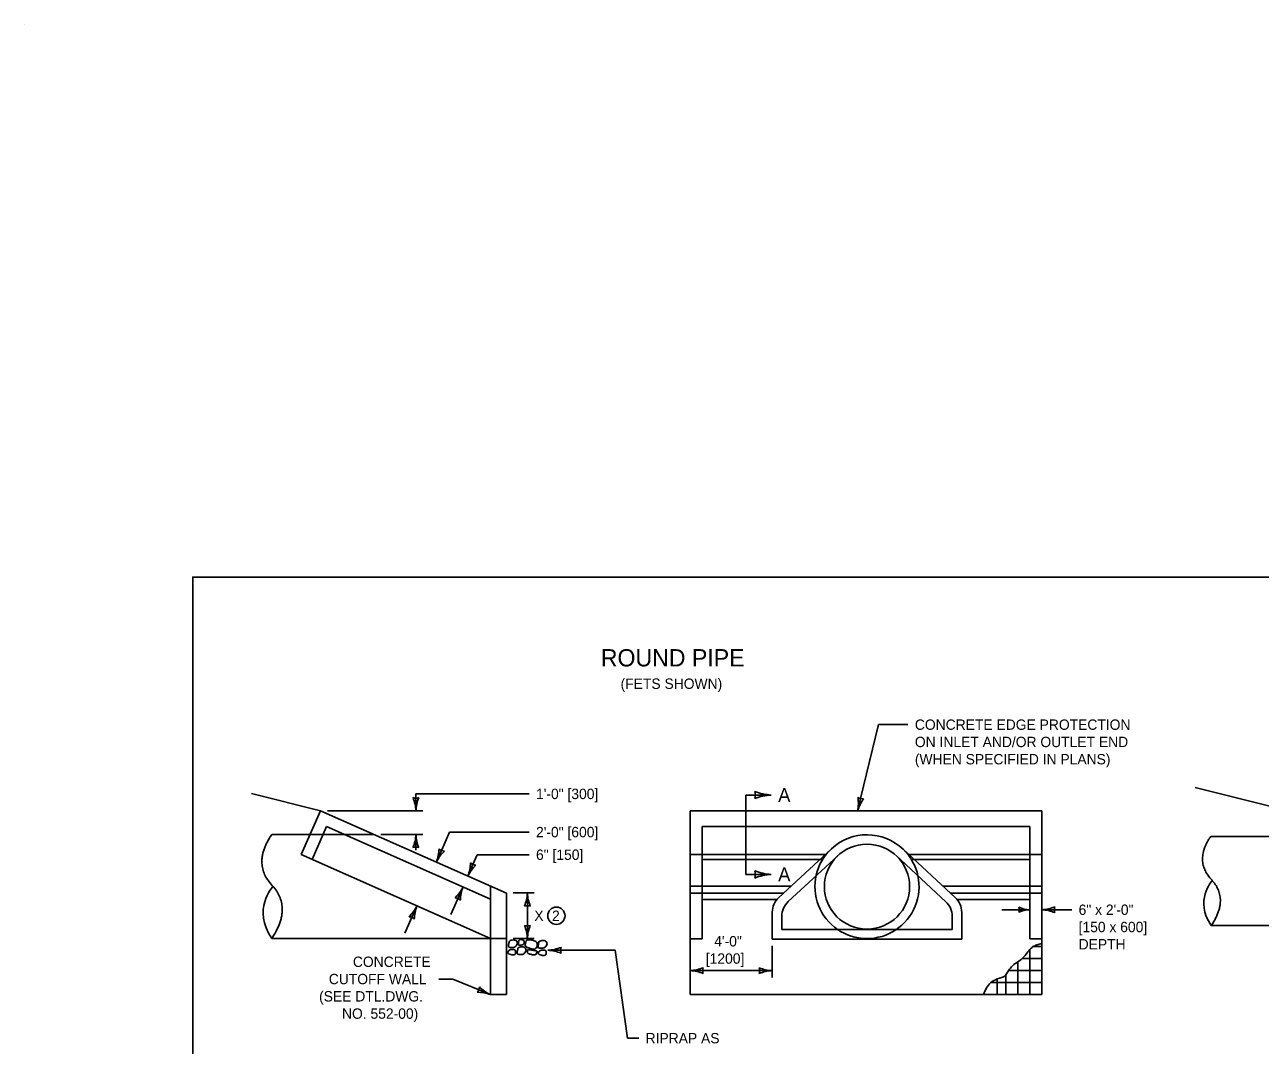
# Model space of a CAD drawing. Extents: x 49991.4 to 50021, y 49987.6 to 50011.4.
# Drawn here: x 50008.76 to 50015.92, y 50005.45 to 50011.36 of the extents above; entities that cross this region are included whole.
import ezdxf

# ---------------------------------------------------------------- set-up
doc = ezdxf.new("R2010")
doc.units = 0
for name, color, linetype in [('Level 1', 7, 'Continuous'), ('Level 2', 7, 'Continuous'), ('Level 3', 7, 'Continuous'), ('Level 4', 7, 'Continuous'), ('Level 6', 7, 'Continuous')]:
    doc.layers.add(name, color=color, linetype=linetype)

msp = doc.modelspace()

# ---------------------------------------------------------------- linework, layer by layer
at = {"layer": 'Level 1'}
for p, q in [((50008.7646, 50011.3628), (50008.7646, 50011.3628)), ((50010.477, 50006.8119), (50010.077, 50006.9119)), ((50016.1364, 50006.7969), (50015.5405, 50006.9461)), ((50010.477, 50006.8119), (50010.3648, 50006.558)), ((50011.5532, 50006.3359), (50010.477, 50006.8119)), ((50012.6169, 50006.8119), (50014.6523, 50006.8119)), ((50012.6169, 50005.7479), (50012.6169, 50006.8119)), ((50014.6523, 50005.7479), (50014.6523, 50006.8119)), ((50010.4164, 50006.6748), (50010.1952, 50006.6748)), ((50016.0887, 50006.6627), (50015.6302, 50006.6627)), ((50013.435, 50006.5923), (50013.1292, 50006.3081)), ((50013.8501, 50006.5889), (50014.1521, 50006.3081)), ((50011.4607, 50006.0733), (50010.3648, 50006.558)), ((50013.4729, 50006.5528), (50013.1842, 50006.2861)), ((50013.8087, 50006.5527), (50014.0973, 50006.2855)), ((50011.4607, 50005.7479), (50011.4607, 50006.3768)), ((50012.6169, 50006.3755), (50013.2017, 50006.3755)), ((50014.0796, 50006.3755), (50014.6523, 50006.3755)), ((50011.5532, 50005.7479), (50011.5532, 50006.3359)), ((50012.6169, 50006.3359), (50013.1591, 50006.3359)), ((50014.1222, 50006.3359), (50014.6523, 50006.3359)), ((50013.0925, 50006.0692), (50013.0926, 50006.2242)), ((50013.1474, 50006.1239), (50013.1474, 50006.202)), ((50014.134, 50006.1239), (50014.1341, 50006.2015)), ((50014.1888, 50006.0692), (50014.1889, 50006.224)), ((50014.134, 50006.1239), (50013.1474, 50006.1239)), ((50017.1373, 50006.1472), (50015.6335, 50006.1472)), ((50011.4607, 50006.0733), (50010.1948, 50006.0733)), ((50011.619, 50006.0174), (50011.6203, 50006.0182)), ((50011.7402, 50006.0538), (50011.7415, 50006.0546)), ((50014.1888, 50006.0692), (50013.0925, 50006.0692)), ((50014.6015, 50006.0255), (50014.6523, 50006.0255)), ((50014.5395, 50005.9561), (50014.6523, 50005.9561)), ((50014.5829, 50005.7479), (50014.5829, 50006.0083)), ((50014.4599, 50005.8867), (50014.6523, 50005.8867)), ((50014.5135, 50005.7479), (50014.5135, 50005.9377)), ((50014.3576, 50005.8174), (50014.6523, 50005.8174)), ((50014.3937, 50005.7479), (50014.3937, 50005.8387)), ((50014.4442, 50005.7479), (50014.4442, 50005.8616)), ((50011.4607, 50005.7479), (50011.5532, 50005.7479)), ((50012.6169, 50005.7479), (50014.6523, 50005.7479))]:
    msp.add_line(p, q, dxfattribs=at)
msp.add_lwpolyline([(50020.9378, 50008.1646), (50009.7374, 50008.1646), (50009.7374, 49999.8856), (50020.9378, 49999.8856)], close=True, dxfattribs=at)
for centre, major_axis, start_param, end_param in [((50013.6407, 50006.3727), (0.3015, 0), 0.803192, 2.321661), ((50013.2077, 50006.2242), (-0.1151, 0), 5.463072, 6.283185), ((50014.0738, 50006.224), (0.1151, 0), 0, 0.82267), ((50013.2625, 50006.202), (-0.1151, 0), 5.460236, 6.283185), ((50014.019, 50006.2015), (0.1151, 0), 0, 0.822133)]:
    msp.add_ellipse(centre, major_axis=major_axis, ratio=0.996203, start_param=start_param, end_param=end_param, dxfattribs=at)
msp.add_ellipse((50013.6407, 50006.3727), major_axis=(0.2467, 0), ratio=0.996203, dxfattribs=at)
for points, degree in [([(50010.1948, 50006.0733), (50010.3154, 50006.2517), (50010.079, 50006.5076), (50010.1952, 50006.6748)], 2), ([(50015.6335, 50006.1472), (50015.7379, 50006.3016), (50015.5332, 50006.5232), (50015.6302, 50006.6627)], 2), ([(50010.202, 50006.3743), (50010.1995, 50006.3714), (50010.0786, 50006.2405), (50010.1948, 50006.0733)], 3), ([(50015.6397, 50006.4078), (50015.6375, 50006.4052), (50015.5329, 50006.292), (50015.6335, 50006.1472)], 3)]:
    msp.add_open_spline(points, degree=degree, dxfattribs=at)
for points in [[(50011.5703, 50006.0579), (50011.5809, 50006.0625), (50011.5936, 50006.0641), (50011.6069, 50006.0618), (50011.613, 50006.0566), (50011.617, 50006.0456), (50011.6124, 50006.0339), (50011.5994, 50006.0219), (50011.5871, 50006.0204), (50011.5744, 50006.0207), (50011.5664, 50006.0237), (50011.5652, 50006.0334), (50011.5667, 50006.0413), (50011.5685, 50006.0498), (50011.5703, 50006.0579)], [(50011.619, 50006.0174), (50011.6311, 50006.0224), (50011.6437, 50006.0242), (50011.6569, 50006.0217), (50011.6632, 50006.0165), (50011.6672, 50006.0055), (50011.6625, 50005.9938), (50011.6495, 50005.9819), (50011.6373, 50005.9802), (50011.6245, 50005.9807), (50011.6165, 50005.9835), (50011.6152, 50005.9932), (50011.6169, 50006.0012), (50011.6186, 50006.0098), (50011.6203, 50006.0182)], [(50011.626, 50006.0615), (50011.6317, 50006.066), (50011.6435, 50006.0652), (50011.6541, 50006.0607), (50011.6565, 50006.0487), (50011.6498, 50006.0372), (50011.6382, 50006.0339), (50011.6223, 50006.0365), (50011.6223, 50006.0442), (50011.6245, 50006.0519), (50011.6242, 50006.0597), (50011.6262, 50006.062)], [(50011.6618, 50006.0375), (50011.6665, 50006.0514), (50011.6717, 50006.0635), (50011.6792, 50006.0653), (50011.6956, 50006.0648), (50011.7147, 50006.0581), (50011.729, 50006.05), (50011.732, 50006.0339), (50011.7241, 50006.0157), (50011.7126, 50006.0114), (50011.6871, 50006.0171), (50011.6703, 50006.0227), (50011.6623, 50006.032), (50011.6618, 50006.0377)], [(50011.7402, 50006.0538), (50011.7523, 50006.0588), (50011.7649, 50006.0606), (50011.7781, 50006.0581), (50011.7844, 50006.0529), (50011.7884, 50006.0419), (50011.7837, 50006.0302), (50011.7707, 50006.0183), (50011.7585, 50006.0166), (50011.7457, 50006.0171), (50011.7377, 50006.0199), (50011.7364, 50006.0296), (50011.7381, 50006.0376), (50011.7398, 50006.0462), (50011.7415, 50006.0546)], [(50014.3937, 50005.8387), (50014.4442, 50005.8616), (50014.4599, 50005.8867), (50014.5135, 50005.9377), (50014.5395, 50005.9561), (50014.5829, 50006.0083), (50014.6015, 50006.0255)], [(50014.6015, 50006.0255), (50014.6239, 50006.036), (50014.6521, 50006.0419), (50014.6523, 50006.0419)], [(50011.5753, 50006.0083), (50011.5827, 50006.0092), (50011.5912, 50006.009), (50011.6002, 50006.0084), (50011.6045, 50006.0042), (50011.6055, 50005.9927), (50011.6054, 50005.9835), (50011.5953, 50005.9787), (50011.5731, 50005.9811), (50011.5616, 50005.9867), (50011.5624, 50005.9956), (50011.5677, 50006.0025), (50011.5765, 50006.0087)], [(50011.6795, 50006.0094), (50011.6914, 50006.0062), (50011.7093, 50006.0037), (50011.7281, 50006.0004), (50011.7314, 50005.9981), (50011.7281, 50005.987), (50011.7216, 50005.9797), (50011.7036, 50005.9789), (50011.6841, 50005.9843), (50011.6745, 50005.9893), (50011.6746, 50005.9985), (50011.6778, 50006.0076), (50011.6789, 50006.0094)], [(50011.7523, 50006.0045), (50011.7594, 50006.0057), (50011.768, 50006.0053), (50011.7772, 50006.0047), (50011.7814, 50006.0004), (50011.7824, 50005.9891), (50011.7822, 50005.9798), (50011.7721, 50005.975), (50011.7499, 50005.9773), (50011.7385, 50005.9829), (50011.7394, 50005.9918), (50011.7444, 50005.9987), (50011.7517, 50006.0044)], [(50014.3152, 50005.7479), (50014.3578, 50005.8175), (50014.3937, 50005.8387)]]:
    msp.add_spline(points, degree=3, dxfattribs=at)
at = {"layer": 'Level 2'}
msp.add_circle((50011.8424, 50006.2041), 0.05, dxfattribs=at)
at = {"layer": 'Level 3'}
for p, q in [((50013.7069, 50007.3106), (50013.5863, 50006.8119)), ((50013.7069, 50007.3106), (50013.8778, 50007.3106)), ((50011.0293, 50006.8119), (50011.0293, 50006.9097)), ((50011.0293, 50006.9097), (50011.6846, 50006.9097)), ((50010.517, 50006.8119), (50011.0693, 50006.8119)), ((50010.8269, 50006.6748), (50011.0692, 50006.6748)), ((50011.0292, 50006.5841), (50011.0292, 50006.6748)), ((50011.1478, 50006.5152), (50011.2245, 50006.6886)), ((50011.2245, 50006.6886), (50011.6846, 50006.6886)), ((50011.3303, 50006.4345), (50011.3845, 50006.5576)), ((50011.3845, 50006.5576), (50011.6846, 50006.5576)), ((50011.2323, 50006.2124), (50011.3023, 50006.3711)), ((50011.5932, 50006.336), (50011.7146, 50006.336)), ((50011.6746, 50006.336), (50011.6747, 50006.0723)), ((50010.9653, 50006.1028), (50011.0353, 50006.2614)), ((50014.4217, 50006.2391), (50014.5829, 50006.2391)), ((50014.6523, 50006.2391), (50014.8257, 50006.2391)), ((50011.5932, 50006.0723), (50011.7147, 50006.0723)), ((50013.0925, 50005.8466), (50013.0925, 50006.0292)), ((50011.7935, 50006.0044), (50012.1834, 50006.0044)), ((50012.1834, 50006.0044), (50012.2551, 50005.4954)), ((50013.0925, 50005.8866), (50012.6169, 50005.8866)), ((50011.1617, 50005.8378), (50011.2436, 50005.8378)), ((50011.2436, 50005.8378), (50011.4607, 50005.7479)), ((50012.2551, 50005.4954), (50012.3189, 50005.4954))]:
    msp.add_line(p, q, dxfattribs=at)
for centre, radius, start, end in [((50011.0293, 50006.9401), 0.0548, 252.13882, 287.86118), ((50010.7966, 50006.8004), 0.233, 2.82731, 22.07716), ((50011.2514, 50006.8027), 0.2223, 157.45601, 177.63952), ((50013.0976, 50007.1809), 0.2779, 247.45601, 267.63952), ((50012.9259, 50006.9032), 0.0685, 342.13882, 17.86118), ((50013.1006, 50006.6123), 0.2912, 92.82731, 112.07716), ((50013.3577, 50006.8568), 0.233, 348.8782, 8.12805), ((50013.7997, 50006.7495), 0.2223, 143.5069, 163.69041), ((50013.6172, 50006.9363), 0.0548, 238.18971, 273.91207), ((50010.8071, 50006.684), 0.2223, 337.45601, 357.63952), ((50011.2619, 50006.6863), 0.233, 182.82731, 202.07716), ((50011.0292, 50006.5466), 0.0548, 72.13882, 107.86118), ((50010.9303, 50006.5989), 0.233, 338.95328, 358.20312), ((50011.1997, 50006.6325), 0.0548, 228.26478, 263.98714), ((50011.3472, 50006.4169), 0.2223, 133.58197, 153.76548), ((50011.1127, 50006.5178), 0.233, 339.05124, 358.30109), ((50011.5299, 50006.3366), 0.2223, 133.67994, 153.86345), ((50011.382, 50006.5518), 0.0548, 228.36275, 264.08511), ((50013.0976, 50006.7214), 0.2779, 247.45601, 267.63952), ((50012.9259, 50006.4437), 0.0685, 342.13882, 17.86118), ((50013.1006, 50006.1528), 0.2912, 92.82731, 112.07716), ((50011.1028, 50006.4691), 0.2223, 313.64287, 333.82638), ((50011.2505, 50006.2538), 0.0548, 48.32568, 84.04804), ((50011.5198, 50006.2876), 0.233, 159.01417, 178.26402), ((50011.4525, 50006.3452), 0.2223, 337.45601, 357.63952), ((50011.9073, 50006.3475), 0.233, 182.82731, 202.07716), ((50010.8358, 50006.3596), 0.2223, 313.63372, 333.81723), ((50011.2529, 50006.178), 0.233, 159.00502, 178.25487), ((50011.6746, 50006.2078), 0.0548, 72.13882, 107.86118), ((50014.5905, 50006.4242), 0.1853, 247.45601, 267.63952), ((50014.4761, 50006.2391), 0.0456, 342.13882, 17.86118), ((50014.5925, 50006.0452), 0.1942, 92.82731, 112.07716), ((50014.6408, 50006.4718), 0.233, 272.82731, 292.07716), ((50014.6431, 50006.017), 0.2223, 67.45601, 87.63952), ((50014.7805, 50006.2391), 0.0548, 162.13882, 197.86118), ((50010.9836, 50006.1442), 0.0548, 48.31653, 84.03889), ((50011.6747, 50006.2005), 0.0548, 252.13882, 287.86118), ((50011.442, 50006.0608), 0.233, 2.82731, 22.07716), ((50011.8968, 50006.0631), 0.2223, 157.45601, 177.63952), ((50011.782, 50006.2371), 0.233, 272.82731, 292.07716), ((50011.9217, 50006.0044), 0.0548, 162.13882, 197.86118), ((50011.7843, 50005.7823), 0.2223, 67.45601, 87.63952), ((50012.6054, 50006.1193), 0.233, 272.82731, 292.07716), ((50012.6077, 50005.6645), 0.2223, 67.45601, 87.63952), ((50012.7451, 50005.8866), 0.0548, 162.13882, 197.86118), ((50013.1017, 50006.1087), 0.2223, 247.45601, 267.63952), ((50012.9643, 50005.8866), 0.0548, 342.13882, 17.86118), ((50013.104, 50005.6539), 0.233, 92.82731, 112.07716), ((50011.3422, 50005.7969), 0.0548, 319.64694, 355.3693), ((50011.3842, 50005.5392), 0.2223, 69.8686, 90.05211), ((50011.5603, 50005.9585), 0.233, 225.43096, 244.68081)]:
    msp.add_arc(centre, radius, start, end, dxfattribs=at)
at = {"layer": 'Level 4'}
for p, q in [((50010.4164, 50006.6748), (50010.787, 50006.6748)), ((50010.5124, 50006.7204), (50010.4282, 50006.5299)), ((50011.4607, 50006.301), (50010.5124, 50006.7204)), ((50012.6864, 50006.7204), (50014.5829, 50006.7204)), ((50012.6864, 50006.0709), (50012.6864, 50006.7204)), ((50014.5829, 50006.0709), (50014.5829, 50006.7204)), ((50012.6169, 50006.558), (50013.4034, 50006.558)), ((50012.6864, 50006.5301), (50013.384, 50006.5301)), ((50013.878, 50006.558), (50014.6523, 50006.558)), ((50013.8975, 50006.5301), (50014.5829, 50006.5301)), ((50012.6864, 50006.2975), (50013.1192, 50006.2975)), ((50014.1622, 50006.2975), (50014.5829, 50006.2975)), ((50011.5532, 50006.0733), (50011.4607, 50006.0733)), ((50012.6169, 50006.0709), (50012.6864, 50006.0709)), ((50014.5829, 50006.0709), (50014.6523, 50006.0709))]:
    msp.add_line(p, q, dxfattribs=at)
msp.add_ellipse((50013.6407, 50006.3727), major_axis=(0.3015, 0), ratio=0.996203, start_param=2.321661, end_param=7.086377, dxfattribs=at)
at = {"layer": 'Level 6'}
for p, q in [((50012.9394, 50006.9032), (50013.0862, 50006.9032)), ((50012.9394, 50006.4437), (50012.9394, 50006.9032)), ((50012.9394, 50006.4437), (50013.0862, 50006.4437))]:
    msp.add_line(p, q, dxfattribs=at)

# ---------------------------------------------------------------- texts
at = {"layer": 'Level 2'}
for s, height, p in [('ROUND PIPE', 0.1, (50012.0997, 50007.6477)), ('(FETS SHOWN)', 0.06, (50012.2143, 50007.5177)), ('CONCRETE EDGE PROTECTION', 0.06, (50013.9178, 50007.2806)), ('ON INLET AND/OR OUTLET END', 0.06, (50013.9178, 50007.1806)), ('(WHEN SPECIFIED IN PLANS)', 0.06, (50013.9178, 50007.0806)), ('1\'-0" [300]', 0.06, (50011.7246, 50006.8797)), ('A', 0.08, (50013.1262, 50006.8632)), ('2\'-0" [600]', 0.06, (50011.7246, 50006.6586)), ('6" [150]', 0.06, (50011.7246, 50006.5276)), ('A', 0.08, (50013.1262, 50006.4037)), ('X', 0.06, (50011.7147, 50006.1741)), ('2', 0.06, (50011.8173, 50006.1741)), ('6" x 2\'-0"', 0.06, (50014.8657, 50006.2091)), ('[150 x 600]', 0.06, (50014.8657, 50006.1091)), ('4\'-0"', 0.06, (50012.7562, 50006.0266)), ('DEPTH', 0.06, (50014.8657, 50006.0091)), ('CONCRETE', 0.06, (50010.6645, 50005.9078)), ('[1200]', 0.06, (50012.7075, 50005.9266)), ('CUTOFF WALL', 0.06, (50010.525, 50005.8078)), ('(SEE DTL.DWG.', 0.06, (50010.4687, 50005.7078)), ('NO. 552-00)', 0.06, (50010.6014, 50005.6078)), ('RIPRAP AS', 0.06, (50012.3589, 50005.4654))]:
    msp.add_text(s, height=height, dxfattribs=at).set_placement(p)

doc.saveas('drawing.dxf')
